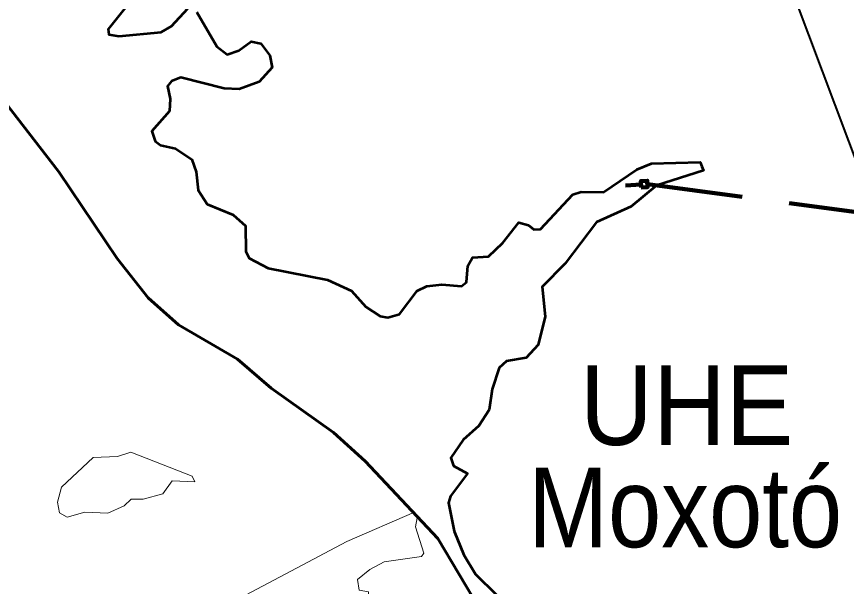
# Model space of a CAD drawing. Extents: x -1643653 to 4543381, y 1624270 to 13878484.
# Drawn here: x 584359 to 589576, y 8965010 to 8968594 of the extents above; entities that cross this region are included whole.
import ezdxf
from ezdxf.enums import TextEntityAlignment as Align

# ---------------------------------------------------------------- set-up
doc = ezdxf.new("R2010")
doc.units = 0
doc.header["$LTSCALE"] = 200
doc.linetypes.add('LONG_DASH_SHORT_DASH', pattern=[9.9, 6, -1.2, 1.5, -1.2])
doc.linetypes.add('MEDIUM_DASHED', pattern=[4.5, 3, -1.5])
for name, color, linetype, lineweight in [('12', 7, 'Continuous', 25), ('25', 7, 'Continuous', 13), ('28', 7, 'Continuous', 53), ('60', 7, 'Continuous', 13), ('61', 7, 'Continuous', 90), ('7', 7, 'LONG_DASH_SHORT_DASH', 60)]:
    doc.layers.add(name, color=color, linetype=linetype, lineweight=lineweight)
doc.layers.add('42', color=7, linetype='Continuous')

msp = doc.modelspace()

# ---------------------------------------------------------------- linework, layer by layer
at = {"layer": '12', "lineweight": 40}
msp.add_lwpolyline([(586230.8, 8974340.1), (586568.3, 8973894.4), (586761.1, 8973701.7), (586961.6, 8973436.3), (587301, 8972874.3), (587640.4, 8972251.7), (587788.5, 8972042.4), (588207.4, 8971376.7), (588263.1, 8971248.8), (588483.5, 8970850.8), (588695.4, 8970396.6), (588857.5, 8969895.4), (589190.3, 8968987.7), (589251, 8968710.7), (589674.6, 8967582.3), (589899.5, 8967058.9), (590052.2, 8966645.4), (590154.6, 8966267.7), (590247.4, 8965995.5), (590238.8, 8965878.8), (590381.4, 8965077.2), (590437.7, 8964620.9)], dxfattribs=at)
at = {"layer": '25'}
for points in [[(585077.6, 8968692.1), (584933.7, 8968514.1), (584939.8, 8968481.6), (585001.2, 8968471), (585266.9, 8968496.5), (585333.9, 8968534), (585434.5, 8968644.9)], [(585077.6, 8968692.1), (584933.7, 8968514.1), (584939.8, 8968481.6), (585001.2, 8968471), (585266.9, 8968496.5), (585333.9, 8968534), (585434.5, 8968644.9)], [(585492.3, 8968621), (585617.4, 8968405), (585683.3, 8968356.3), (585757.2, 8968379.6), (585833.8, 8968436.8), (585893.9, 8968423.6), (585950.2, 8968348.5), (585965.4, 8968274.1), (585883, 8968184.3), (585757.4, 8968137.5), (585664, 8968141.7), (585392.1, 8968211.7), (585332.8, 8968188.5), (585307.1, 8968156.3), (585324, 8968076.1), (585319.8, 8967999.4)], [(585492.3, 8968621), (585617.4, 8968405), (585683.3, 8968356.3), (585757.2, 8968379.6), (585833.8, 8968436.8), (585893.9, 8968423.6), (585950.2, 8968348.5), (585965.4, 8968274.1), (585883, 8968184.3), (585757.4, 8968137.5), (585664, 8968141.7), (585392.1, 8968211.7), (585332.8, 8968188.5), (585307.1, 8968156.3), (585324, 8968076.1), (585319.8, 8967999.4)], [(585319.8, 8967999.4), (585209.4, 8967874), (585230.7, 8967810.4), (585264.6, 8967784.9), (585358.3, 8967763.5), (585460, 8967695.5), (585487.7, 8967616.8), (585500.5, 8967502.3), (585557.8, 8967413.1), (585721.3, 8967347.2), (585797.8, 8967276.9), (585799.9, 8967116.4), (585821.7, 8967075), (585940.4, 8967011.6), (586314, 8966937.2), (586464.8, 8966869.3), (586554.2, 8966767.2), (586645.4, 8966710), (586692.1, 8966701.5), (586766.2, 8966722.7), (586877, 8966869.2), (586938.3, 8966898.9), (587031.7, 8966909.6), (587155.3, 8966899.2), (587187, 8966922.6), (587195.6, 8967026.5), (587225.2, 8967079.4), (587325, 8967083.9), (587416.4, 8967171), (587516.5, 8967298.4), (587577.2, 8967281.7), (587609.8, 8967253.9), (587652.2, 8967256), (587856.2, 8967474.6), (587908.7, 8967491.8), (588049.3, 8967489.5), (588259.2, 8967631.5), (588349.7, 8967670.3), (588657.3, 8967677.5), (588667.8, 8967651.8)], [(585319.8, 8967999.4), (585209.4, 8967874), (585230.7, 8967810.4), (585264.6, 8967784.9), (585358.3, 8967763.5), (585460, 8967695.5), (585487.7, 8967616.8), (585500.5, 8967502.3), (585557.8, 8967413.1), (585721.3, 8967347.2), (585797.8, 8967276.9), (585799.9, 8967116.4), (585821.7, 8967075), (585940.4, 8967011.6), (586314, 8966937.2), (586464.8, 8966869.3), (586554.2, 8966767.2), (586645.4, 8966710), (586692.1, 8966701.5), (586766.2, 8966722.7), (586877, 8966869.2), (586938.3, 8966898.9), (587031.7, 8966909.6), (587155.3, 8966899.2), (587187, 8966922.6), (587195.6, 8967026.5), (587225.2, 8967079.4), (587325, 8967083.9), (587416.4, 8967171), (587516.5, 8967298.4), (587577.2, 8967281.7), (587609.8, 8967253.9), (587652.2, 8967256), (587856.2, 8967474.6), (587908.7, 8967491.8), (588049.3, 8967489.5), (588259.2, 8967631.5), (588349.7, 8967670.3), (588657.3, 8967677.5), (588667.8, 8967651.8)], [(588667.8, 8967651.8), (588678.2, 8967626.5), (588381.1, 8967532.1), (588221.7, 8967398.4), (588005.1, 8967300.6), (587807.3, 8967041.3), (587663.1, 8966894.9), (587682, 8966707.8), (587637.4, 8966529.4), (587563.2, 8966446.7), (587438, 8966427.4), (587392.7, 8966384.2), (587348.6, 8966249.6), (587329.2, 8966121.3), (587265.6, 8966019.6), (587165.8, 8965932.5), (587089.5, 8965818), (587106.5, 8965769), (587193.3, 8965719.9), (587087.2, 8965577.5), (587074.5, 8965534.6), (587110.7, 8965356.6), (587170.4, 8965207.5), (587244.3, 8965087.2), (587376.1, 8964957.5)], [(588667.8, 8967651.8), (588678.2, 8967626.5), (588381.1, 8967532.1), (588221.7, 8967398.4), (588005.1, 8967300.6), (587807.3, 8967041.3), (587663.1, 8966894.9), (587682, 8966707.8), (587637.4, 8966529.4), (587563.2, 8966446.7), (587438, 8966427.4), (587392.7, 8966384.2), (587348.6, 8966249.6), (587329.2, 8966121.3), (587265.6, 8966019.6), (587165.8, 8965932.5), (587089.5, 8965818), (587106.5, 8965769), (587193.3, 8965719.9), (587087.2, 8965577.5), (587074.5, 8965534.6), (587110.7, 8965356.6), (587170.4, 8965207.5), (587244.3, 8965087.2), (587376.1, 8964957.5)]]:
    msp.add_lwpolyline(points, dxfattribs=at)
for points in [[(585077.7, 8965854), (584992.7, 8965826.3), (584839.9, 8965820.3), (584642.3, 8965632.9), (584616.8, 8965540.1), (584629.5, 8965471.6), (584675.9, 8965446), (584789, 8965475.7), (584933.4, 8965469.6), (585035.3, 8965516.3), (585079.8, 8965558.5), (585154.1, 8965558.7), (585279.1, 8965592.6), (585337.4, 8965673.5), (585478.9, 8965666.9), (585463.8, 8965703.2)], [(585077.7, 8965854), (584992.7, 8965826.3), (584839.9, 8965820.3), (584642.3, 8965632.9), (584616.8, 8965540.1), (584629.5, 8965471.6), (584675.9, 8965446), (584789, 8965475.7), (584933.4, 8965469.6), (585035.3, 8965516.3), (585079.8, 8965558.5), (585154.1, 8965558.7), (585279.1, 8965592.6), (585337.4, 8965673.5), (585478.9, 8965666.9), (585463.8, 8965703.2)], [(585439, 8964728.2), (585379.4, 8964639), (585398.5, 8964484), (585440.9, 8964473.3), (585545, 8964564.5), (585884.6, 8964666.3), (586267.5, 8964700.5), (586430.8, 8964740.8), (586553.9, 8964845), (586575.2, 8964881), (586570.7, 8964976.5), (586513.6, 8964985.3), (586501.3, 8965053.3), (586579.7, 8965116.9), (586670.6, 8965163.4), (586903.9, 8965197.4), (586919.2, 8965218.6), (586866.7, 8965384.8), (586876.8, 8965441.6), (586860, 8965477.5), (586435.1, 8965293.1), (585696.3, 8964900.4)], [(585439, 8964728.2), (585379.4, 8964639), (585398.5, 8964484), (585440.9, 8964473.3), (585545, 8964564.5), (585884.6, 8964666.3), (586267.5, 8964700.5), (586430.8, 8964740.8), (586553.9, 8964845), (586575.2, 8964881), (586570.7, 8964976.5), (586513.6, 8964985.3), (586501.3, 8965053.3), (586579.7, 8965116.9), (586670.6, 8965163.4), (586903.9, 8965197.4), (586919.2, 8965218.6), (586866.7, 8965384.8), (586876.8, 8965441.6), (586860, 8965477.5), (586435.1, 8965293.1), (585696.3, 8964900.4)]]:
    msp.add_lwpolyline(points, close=True, dxfattribs=at)
at = {"layer": '28'}
for points in [[(585077.6, 8968692.1), (584933.7, 8968514.1), (584939.8, 8968481.6), (585001.2, 8968471), (585266.9, 8968496.5), (585333.9, 8968534), (585434.5, 8968644.9)], [(585492.3, 8968621), (585617.4, 8968405), (585683.3, 8968356.3), (585757.2, 8968379.6), (585833.8, 8968436.8), (585893.9, 8968423.6), (585950.2, 8968348.5), (585965.4, 8968274.1), (585883, 8968184.3), (585757.4, 8968137.5), (585664, 8968141.7), (585392.1, 8968211.7), (585332.8, 8968188.5), (585307.1, 8968156.3), (585324, 8968076.1), (585319.8, 8967999.4)], [(585319.8, 8967999.4), (585209.4, 8967874), (585230.7, 8967810.4), (585264.6, 8967784.9), (585358.3, 8967763.5), (585460, 8967695.5), (585487.7, 8967616.8), (585500.5, 8967502.3), (585557.8, 8967413.1), (585721.3, 8967347.2), (585797.8, 8967276.9), (585799.9, 8967116.4), (585821.7, 8967075), (585940.4, 8967011.6), (586314, 8966937.2), (586464.8, 8966869.3), (586554.2, 8966767.2), (586645.4, 8966710), (586692.1, 8966701.5), (586766.2, 8966722.7), (586877, 8966869.2), (586938.3, 8966898.9), (587031.7, 8966909.6), (587155.3, 8966899.2), (587187, 8966922.6), (587195.6, 8967026.5), (587225.2, 8967079.4), (587325, 8967083.9), (587416.4, 8967171), (587516.5, 8967298.4), (587577.2, 8967281.7), (587609.8, 8967253.9), (587652.2, 8967256), (587856.2, 8967474.6), (587908.7, 8967491.8), (588049.3, 8967489.5), (588259.2, 8967631.5), (588349.7, 8967670.3), (588657.3, 8967677.5), (588667.8, 8967651.8)], [(588667.8, 8967651.8), (588678.2, 8967626.5), (588381.1, 8967532.1), (588221.7, 8967398.4), (588005.1, 8967300.6), (587807.3, 8967041.3), (587663.1, 8966894.9), (587682, 8966707.8), (587637.4, 8966529.4), (587563.2, 8966446.7), (587438, 8966427.4), (587392.7, 8966384.2), (587348.6, 8966249.6), (587329.2, 8966121.3), (587265.6, 8966019.6), (587165.8, 8965932.5), (587089.5, 8965818), (587106.5, 8965769), (587193.3, 8965719.9), (587087.2, 8965577.5), (587074.5, 8965534.6), (587110.7, 8965356.6), (587170.4, 8965207.5), (587244.3, 8965087.2), (587376.1, 8964957.5)]]:
    msp.add_lwpolyline(points, dxfattribs=at)
at = {"layer": '60', "lineweight": 25}
msp.add_spline([(814781, 9009175.5), (814787.2, 9009173.4), (814796.9, 9009173.4), (814799.4, 9009172.4), (814805.1, 9009174.5), (814805.6, 9009176.5), (814811.7, 9009179.5), (814811.7, 9009179.5), (814801.5, 9009181), (814790.7, 9009181.5), (814784.1, 9009183.1), (814777.4, 9009185.1), (814778.4, 9009175.5)], degree=3, dxfattribs=at)
at = {"layer": '61'}
msp.add_line((588186.7, 8967531.1), (588285, 8967537.4), dxfattribs=at)
at = {"layer": '61', "linetype": 'MEDIUM_DASHED'}
msp.add_line((588325, 8967540), (589948, 8967322.2), dxfattribs=at)
at = {"layer": '61'}
msp.add_lwpolyline([(588286.3, 8967518.8), (588326.2, 8967521.3), (588323.7, 8967561.2), (588283.8, 8967558.7)], close=True, dxfattribs=at)
at = {"layer": '7'}
msp.add_lwpolyline([(583174.4, 8969966), (583327.9, 8969505.4), (583474.7, 8969160.4), (583725.5, 8968684.8), (583883.2, 8968539.9), (583982.9, 8968403.5), (584146.9, 8968235.1), (584624.8, 8967616.6), (584992.2, 8967072.1), (585186.8, 8966825.7), (585377.2, 8966655.9), (585748.8, 8966438.6), (585960.5, 8966257.3), (586351.6, 8965976.8), (586551, 8965796.4), (587006.6, 8965310.9), (587303.1, 8964815.2), (587426.7, 8964495.3)], dxfattribs=at)

# ---------------------------------------------------------------- texts
at = {"layer": '42'}
for s, width, p in [('UHE', 0.95, (588571.1, 8965899.4)), ('Moxotó', 0.9, (588562.6, 8965256.2))]:
    msp.add_text(s, height=500, dxfattribs=dict(at, width=width)).set_placement(p, align=Align.CENTER)

doc.saveas('drawing.dxf')
